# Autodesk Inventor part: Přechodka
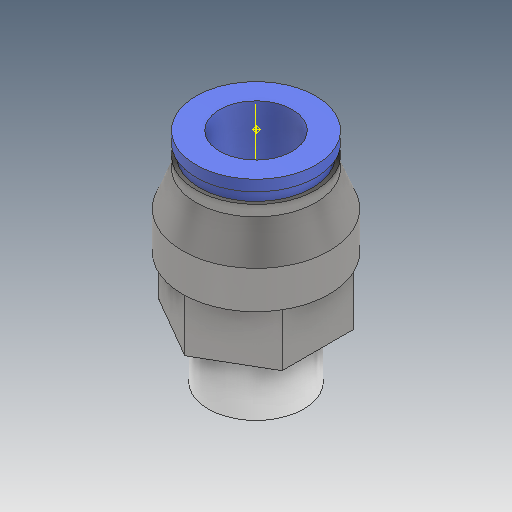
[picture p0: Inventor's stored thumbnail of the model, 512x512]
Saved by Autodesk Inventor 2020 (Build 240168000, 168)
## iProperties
Created: 2019-03
Part Number: Přechodka
Material: Ocel
Description: STEP AP214
Document SubType Name: Modeling
Designer: doma
Density: 7.85 g/cm^3
Appearance: Plech
Mass: 37.2712 g
Surface Area: 30.0383 cm^2
Volume: 4.74793 cm^3
Sending System: SolidWorks 2017
Preprocessor: SwSTEP 2.0
Title: CONEXÃO RETA.STEP
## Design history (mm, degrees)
feature "Ø10 x 1-4G - CONEXÃO RETA (C02251028)_16:1"
node "Pracovní osa1"
node "Pracovní bod1"
node "Pracovní bod2"
node "Těleso1"
node "Těleso16"
